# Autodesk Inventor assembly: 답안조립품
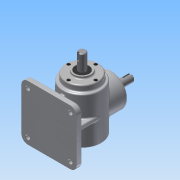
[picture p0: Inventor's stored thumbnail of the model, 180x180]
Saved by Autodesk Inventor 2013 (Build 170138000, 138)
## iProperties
Created: 2015-07
Part Number: 답안조립품
Document SubType Name: Assembly
Designer: Administrator
Author: Administrator
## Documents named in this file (14)
- C:\Users\Administrator\Desktop\450706V1018\답안조립품.iam
- C:\Users\Administrator\Desktop\450706V1018\본체.ipt
- C:\Users\Administrator\Desktop\450706V1018\메인 베벨기어.ipt
- C:\Users\Administrator\Desktop\450706V1018\메인 축.ipt
- 메인 축.ipt
- C:\Users\Administrator\Desktop\450706V1018\베어링 6203.ipt
- C:\Users\Administrator\Desktop\450706V1018\오일실.ipt
- C:\Users\Administrator\Desktop\450706V1018\커버.ipt
- C:\Users\Administrator\Desktop\450706V1018\키 5x5.ipt
- C:\Users\Administrator\Desktop\450706V1018\서브 베벨기어.ipt
- C:\Users\Administrator\Desktop\450706V1018\서브 축.ipt
- 서브 축.ipt
- C:\Users\Administrator\Desktop\450706V1018\키 4x4.ipt
- C:\Users\Administrator\Desktop\450706V1018\M4.ipt
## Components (8 placed, 1 different names)
1. M4:1
2. M4:2
3. M4:3
4. M4:4
5. M4:5
6. M4:6
7. M4:7
8. M4:8
